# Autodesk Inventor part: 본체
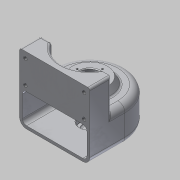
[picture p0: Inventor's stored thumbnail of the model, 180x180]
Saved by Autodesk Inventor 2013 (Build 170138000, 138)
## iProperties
Created: 2015-02
Part Number: 본체
Material: 알루미늄 6061
Document SubType Name: Modeling
Designer: Administrator
Density: 2.71 g/cm^3
Mass: 613.246 g
Surface Area: 709.081 cm^2
Volume: 226.29 cm^3
Author: Administrator
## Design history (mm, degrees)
sketch "스케치1"
  geometry: L1 (-50, -50)-(50, -50); L2 (-50, 0)-(-50, -50); L3 (50, 0)-(50, -50); A1 r 50 centre (0, 0) between (50, 0) and (-50, 0); 1 further point
  constraints: 6 end point, 2 point on circle, 2 tangent, 1 centre point, 1 coincident, 1 horizontal, 1 parallel, 1 perpendicular
  dimensions: "d0" = 100 diameter of A1; "d2" = 50 distance from line of L1 point (0, 0)
extrude "돌출1" new body sketch "스케치1" distance "d3" = 50; taper "d4" = 0 deg
node "작업 평면1"
feature "쉘1" dims "d9" = 4
sketch "스케치2"
  geometry: L1 (50, -20)-(-50, -20); L2 (-50, -20)-(-50, -50); L3 (-50, -50)-(50, -50); L4 (50, -50)-(50, -20); L5 (50, 0)-(50, -50) reference; L6 (50, -50)-(-50, -50) reference; L7 (-50, -50)-(-50, 0) reference; 1 further point
  constraints: 8 end point, 2 parallel, 1 horizontal, 1 perpendicular
  dimensions: "d6" = 30 distance of L1.end L2.end
extrude "돌출2" join sketch "스케치2" stored distance "d7" = 50; taper "d8" = 0 deg
sketch "스케치4"
  geometry: C1 r 40 at (0, 0); 1 further point
  constraints: 1 centre point, 1 coincident
  dimensions: "d12" = 80 diameter of C1
extrude "돌출3" cut sketch "스케치4" stored distance "d14" = 50; taper "d15" = 0 deg
sketch "스케치5"
  geometry: L1 (100, 0)-(100, 95) reference; L2 (100, 95)-(0, 95) reference; 5 further points
  constraints: 2 horizontal alignment, 2 vertical alignment
  dimensions: "d16" = 33 distance of point (91.75, 53) point (91.75, 86); "d18" = 83.5 distance of point (91.75, 86) point (8.25, 86); "d19" = 9 distance from line of point (91.75, 86) L2; "d20" = 8.25 distance from line of L1 point (91.75, 86)
hole "구멍1" sketch "스케치5" at (8.25, 86), (8.25, 53), (91.75, 86), (91.75, 53) diameter "d21" = 5.134; stored, may be unused: countersink angle "d25" = 90 deg, drill point angle "d27" = 118 deg; dims "d22" = 10, "d23" = 4, "d24" = 2, "d26" = 13
sketch "스케치8"
  geometry: C1 r 25 at (0, 0); A1 r 40 centre (0, 0) between (-34.641, -20) and (34.641, -20) reference
  constraints: 1 centre point, 1 coincident
  dimensions: "d28" = 50 diameter of C1
extrude "돌출4" join sketch "스케치8" distance "d30" = 10; taper "d31" = 0 deg
sketch "스케치9"
  geometry: C1 r 25 at (0, 0); A1 r 50 centre (0, 0) between (50, 0) and (-50, 0) reference
  constraints: 1 centre point, 1 coincident
  dimensions: "d32" = 50 diameter of C1
extrude "돌출5" join sketch "스케치9" distance "d34" = 9; taper "d35" = 0 deg
sketch "스케치10"
  geometry: L1 (0, 69.285)-(0, -69.285); L2 (25, 60)-(-25, 60) reference; L3 (-25, -9)-(25, -9) reference; L4 (0, 60)-(14, 60); L5 (14, 60)-(14, 50); L6 (14, 50)-(10, 50); L7 (10, 50)-(10, 4); L8 (10, 4)-(14, 4); L9 (14, 4)-(14, -4); L10 (14, -4)-(10, -4); L11 (10, -4)-(10, -6); L12 (10, -6)-(0, -6); L13 (46, 4)-(0, 4) reference; L14 (0, 60)-(0, -6); 2 further points
  constraints: 22 end point, 4 parallel, 4 perpendicular, 3 point on line, 2 midpoint, 1 coincident, 1 collinear, 1 vertical
  dimensions: "d36" = 28 diameter of L5 L1; "d38" = 20 diameter of L7 L1; "d39" = 20 diameter of L11 L1; "d40" = 28 diameter of L9 L1; "d41" = 10 distance of L4.end L5.end; "d42" = 8 distance of L8.end L9.end; "d43" = 2 distance between parallel lines of L12 L10
revolve "회전1" sketch "스케치10" stored, may be unused: angle "d44" = 90 deg
fillet "모깎기1" dims "d45" = 10
fillet "모깎기2" dims "d46" = 0.3
fillet "모깎기3" dims "d47" = 2
fillet "모깎기4" dims "d48" = 0.3
fillet "모깎기5" dims "d49" = 3
chamfer "모따기1" distance "d50" = 1; stored, may be unused: second distance "d51" = 2, angle "d52" = 45 deg
sketch "스케치11" dims "d53" = 36
  geometry: C1 r 25 at (0, 0) reference; C2 r 15 at (0, 0) reference; 2 further points
  constraints: 2 vertical alignment, 1 coincident, 2 other
hole "구멍2" sketch "스케치11" at (0, 18) diameter "d55" = 2.459; stored, may be unused: countersink angle "d59" = 90 deg, drill point angle "d61" = 118 deg; dims "d56" = 6, "d57" = 4, "d58" = 2, "d60" = 9
node "작업 평면2"
sketch "스케치12"
  geometry: 2 further points
  constraints: 1 vertical alignment, 1 other
  dimensions: "d65" = 25 distance of point (0, 25) point (0, 0)
feature "엠보싱1" sketch "스케치12" dims "d66" = 0.5, "d67" = 0
chamfer "모따기2" distance "d69" = 1; stored, may be unused: second distance "d70" = 2, angle "d71" = 45 deg
fillet "모깎기7" dims "d72" = 6
fillet "모깎기8" dims "d73" = 3
feature "면 기울기2" dims angle "d76" = 30 deg
fillet "모깎기10" dims "d77" = 3
node "솔리드1"
pattern_circular "원형 패턴1" dims angle "d63" = 360 deg
other parameters: "d5" = -95
